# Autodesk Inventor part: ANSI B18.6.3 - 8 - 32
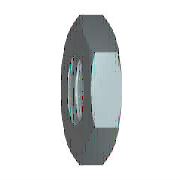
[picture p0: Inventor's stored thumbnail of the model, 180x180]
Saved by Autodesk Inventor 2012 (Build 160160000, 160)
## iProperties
IsCustomPart: 0
Created: 2011-02
Part Number: ANSI B18.6.3 - 8 - 32
Material: Steel, Mild
Description: Hex Machine Screw Nut
Document SubType Name: Modeling
Standard: ANSI B18.6.3
Designer: Owner
Standard Revision: 2003
Standards Organization: ANSI
Language: en-US
Size Designation: 8 - 32
Categories: <MemberInstance><Categories><Category DisplayName="Fasteners" InternalName="e4da775c-781d-43d5-af7c-5136215cf5a6" Mnemonic="FSTN"><Category DisplayName="Nuts" I
Density: 7.86 g/cm^3
Mass: 1.28907 g
Surface Area: 2.23004 cm^2
Volume: 0.164003 cm^3
Author: Owner
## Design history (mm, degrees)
body "Solid1"
workaxis "Work Axis1"
workplane "Work Plane1"
sketch "Sketch1"
  geometry: L1 (-5.045, 0)-(-2.522, 4.369); L2 (-2.522, 4.369)-(2.522, 4.369); L3 (2.522, 4.369)-(5.045, 0); L4 (5.045, 0)-(2.522, -4.369); L5 (2.522, -4.369)-(-2.522, -4.369); L6 (-2.522, -4.369)-(-5.045, 0); 2 further points
  constraints: 12 end point, 1 coincident, 1 horizontal, 11 other
  dimensions: "d0" = 10.08931 distance of L3.end L1.start (= 1.1547 x SW)
extrude "Body" new body sketch "Sketch1" distance "d1" = 2.8956 (= KOH); taper "d2" = 0 deg
revolve "Chamfer1" stored, may be unused: angle "d7" = 90 deg
sketch "Sketch3"
  geometry: A1 r 4.369 centre (0, 0) between (-2.184, -3.783) and (2.184, -3.783) reference; 1 further point
  constraints: 1 coincident
hole "Thread" sketch "Sketch3" diameter "d25" = 3.302; stored, may be unused: countersink angle "d29" = 82 deg, drill point angle "d31" = 118 deg; dims "d26" = 6, "d27" = 4, "d28" = 2, "d30" = 8
chamfer "Chamfer2" distance "d8" = 0.42963 (= -0.5 x GD1 + 0.5 x NND); stored, may be unused: angle "d9" = 30 deg, second distance "d40" = 0.42963 (= -0.5 x GD1 + 0.5 x NND)
chamfer "Chamfer3" distance "d10" = 0.42963 (= -0.5 x GD1 + 0.5 x NND); stored, may be unused: angle "d11" = 30 deg, second distance "d41" = 0.42963 (= -0.5 x GD1 + 0.5 x NND)
sketch "Sketch2"
  geometry: L1 (0, 2.522)-(0, 5.045) reference; L2 (0, 5.045)-(2.896, 5.045) reference; L3 (2.896, 2.522)-(2.896, 5.045) reference; L4 (-0.579, 0)-(3.475, 0) reference; L5 (0.39, 5.045)-(0, 4.369); L6 (2.505, 5.045)-(2.896, 4.369)
  constraints: 4 end point, 4 point on line
  dimensions: "d3" = 30 deg angle of L1 L5 (= ANG1); "d4" = 30 deg angle of L3 L6 (= ANG2); "d5" = 8.7376 diameter of L5.end L4 (= SW0); "d6" = 8.7376 diameter of L6.end L4 (= SW01)
other parameters: "ANG1" = 30 deg [user parameter; used in 1 equation term], "ANG2" = 30 deg [user parameter; used in 1 equation term], "NND" = 4.1656 [user parameter; used in 4 equation terms], "KOH" = 2.8956 [user parameter; used in 1 equation term], "SW" = 8.7376 [user parameter; used in 4 equation terms], "SW0" = 8.7376 (= SW) [user parameter; used in 1 equation term], "SW01" = 8.7376 (= SW) [user parameter; used in 1 equation term], "GD1" = 3.30634 (computed from THREADDIA, PTC, TOA) [user parameter; used in 4 equation terms], "d13" = 0, "d14" = 0, "d39" = 0, "d42" = 0, "THREADDIA" = 4.1656 [user parameter; used in 1 equation term], "TOA" = 30 deg [user parameter; used in 1 equation term], "PTC" = 0.79375 (computed from TPU) [user parameter; used in 1 equation term], "E0" = 10.09193 (= 1.155 x SW) [user parameter]
